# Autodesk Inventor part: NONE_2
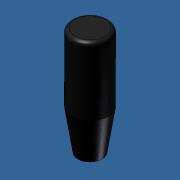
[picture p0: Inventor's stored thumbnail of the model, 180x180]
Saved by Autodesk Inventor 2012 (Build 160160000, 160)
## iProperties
Created: 2013-10
Part Number: NONE_2
Material: Default
Document SubType Name: Modeling
Designer: Admin
Density: 1 g/cm^3
Author: Admin
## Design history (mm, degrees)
node "Sankq_7011P566_Handle1"
node "Base1"
body "Solid1"
